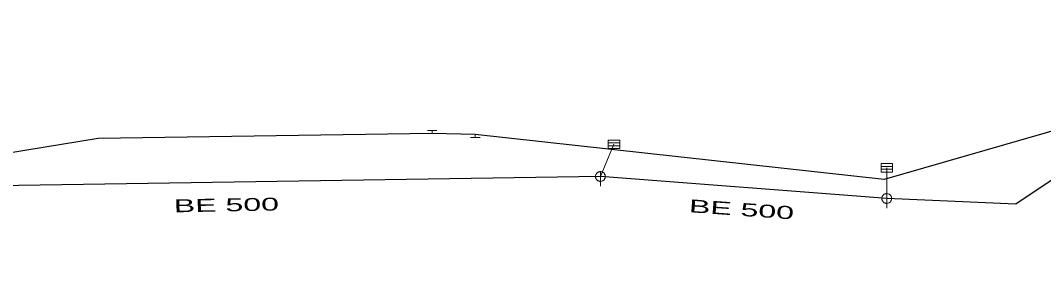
# Model space of a CAD drawing. Extents: x -687468 to -685917, y -974192 to -973456.
# Drawn here: x -686841 to -686788.4, y -973728.6 to -973716 of the extents above; entities that cross this region are included whole.
import ezdxf
from ezdxf.enums import TextEntityAlignment as Align

# ---------------------------------------------------------------- set-up
doc = ezdxf.new("R2010")
doc.units = 0
doc.header["$LTSCALE"] = 0.27
for name, color, linetype, lineweight in [('1', 7, 'Continuous', 13), ('11', 7, 'Continuous', 13), ('14', 7, 'Continuous', 25), ('17', 7, 'Continuous', 25), ('22', 7, 'Continuous', 13), ('34', 7, 'Continuous', 13)]:
    doc.layers.add(name, color=color, linetype=linetype, lineweight=lineweight)

msp = doc.modelspace()

# ---------------------------------------------------------------- linework, layer by layer
at = {"layer": '11'}
for p, q in [((-686810.51, -973722.38), (-686811.2, -973724.04)), ((-686796.46, -973723.59), (-686796.46, -973725.17))]:
    msp.add_line(p, q, dxfattribs=at)
at = {"layer": '14', "lineweight": 13}
for p, q in [((-686819.859, -973721.829), (-686819.859, -973721.669)), ((-686817.64, -973722.03), (-686817.64, -973721.882))]:
    msp.add_line(p, q, dxfattribs=at)
at = {"layer": '14'}
msp.add_line((-686796.46, -973725.17), (-686811.199, -973724.039), dxfattribs=at)
for points in [[(-686778.059, -973717.6), (-686789.822, -973725.456), (-686796.46, -973725.17)], [(-686811.199, -973724.039), (-686842.258, -973724.526), (-686849.73, -973724.67)]]:
    msp.add_lwpolyline(points, dxfattribs=at)
at = {"layer": '17'}
msp.add_lwpolyline([(-686778.16, -973716.008), (-686787.234, -973721.504), (-686796.6, -973724.188), (-686817.64, -973721.881), (-686819.859, -973721.829), (-686837.05, -973722.085), (-686859.074, -973725.682), (-686861.337, -973725.804), (-686883.709, -973728.57)], dxfattribs=at)
at = {"layer": '22'}
for p, q in [((-686810.805, -973722.309), (-686810.207, -973722.309)), ((-686810.805, -973722.455), (-686810.207, -973722.455)), ((-686796.755, -973723.519), (-686796.157, -973723.519)), ((-686796.755, -973723.664), (-686796.157, -973723.664)), ((-686811.198, -973723.787), (-686811.199, -973724.531)), ((-686796.459, -973724.918), (-686796.46, -973725.662))]:
    msp.add_line(p, q, dxfattribs=at)
for points in [[(-686810.805, -973722.163), (-686810.207, -973722.163), (-686810.207, -973722.6), (-686810.805, -973722.6)], [(-686796.755, -973723.373), (-686796.157, -973723.373), (-686796.157, -973723.809), (-686796.755, -973723.809)], [(-686810.947, -973724.039), (-686810.948, -973724.013), (-686810.952, -973723.987), (-686810.958, -973723.961), (-686810.968, -973723.937), (-686810.98, -973723.913), (-686810.994, -973723.891), (-686811.011, -973723.87), (-686811.029, -973723.852), (-686811.05, -973723.835), (-686811.072, -973723.821), (-686811.096, -973723.809), (-686811.12, -973723.799), (-686811.146, -973723.793), (-686811.172, -973723.789), (-686811.198, -973723.787), (-686811.224, -973723.788), (-686811.25, -973723.792), (-686811.276, -973723.798), (-686811.301, -973723.808), (-686811.324, -973723.82), (-686811.346, -973723.834), (-686811.367, -973723.851), (-686811.385, -973723.869), (-686811.402, -973723.89), (-686811.416, -973723.912), (-686811.428, -973723.936), (-686811.438, -973723.96), (-686811.445, -973723.986), (-686811.449, -973724.012), (-686811.451, -973724.038), (-686811.45, -973724.064), (-686811.446, -973724.09), (-686811.439, -973724.116), (-686811.429, -973724.141), (-686811.417, -973724.164), (-686811.403, -973724.186), (-686811.386, -973724.207), (-686811.368, -973724.225), (-686811.347, -973724.242), (-686811.325, -973724.256), (-686811.302, -973724.268), (-686811.277, -973724.278), (-686811.251, -973724.285), (-686811.225, -973724.289), (-686811.199, -973724.291), (-686811.173, -973724.29), (-686811.147, -973724.286), (-686811.121, -973724.279), (-686811.097, -973724.269), (-686811.073, -973724.257), (-686811.051, -973724.243), (-686811.03, -973724.226), (-686811.012, -973724.208), (-686810.995, -973724.187), (-686810.981, -973724.165), (-686810.969, -973724.142), (-686810.959, -973724.117), (-686810.953, -973724.091), (-686810.949, -973724.065)], [(-686796.208, -973725.17), (-686796.209, -973725.144), (-686796.213, -973725.118), (-686796.219, -973725.092), (-686796.229, -973725.068), (-686796.241, -973725.044), (-686796.255, -973725.022), (-686796.272, -973725.001), (-686796.29, -973724.983), (-686796.311, -973724.966), (-686796.333, -973724.952), (-686796.357, -973724.94), (-686796.381, -973724.93), (-686796.407, -973724.924), (-686796.433, -973724.92), (-686796.459, -973724.918), (-686796.485, -973724.919), (-686796.511, -973724.923), (-686796.537, -973724.929), (-686796.562, -973724.939), (-686796.585, -973724.951), (-686796.607, -973724.965), (-686796.628, -973724.982), (-686796.646, -973725), (-686796.663, -973725.021), (-686796.677, -973725.043), (-686796.689, -973725.067), (-686796.699, -973725.091), (-686796.706, -973725.117), (-686796.71, -973725.143), (-686796.712, -973725.169), (-686796.711, -973725.195), (-686796.707, -973725.221), (-686796.7, -973725.247), (-686796.69, -973725.272), (-686796.678, -973725.295), (-686796.664, -973725.317), (-686796.647, -973725.338), (-686796.629, -973725.356), (-686796.608, -973725.373), (-686796.586, -973725.387), (-686796.563, -973725.399), (-686796.538, -973725.409), (-686796.512, -973725.416), (-686796.486, -973725.42), (-686796.46, -973725.422), (-686796.434, -973725.421), (-686796.408, -973725.417), (-686796.382, -973725.41), (-686796.358, -973725.4), (-686796.334, -973725.388), (-686796.312, -973725.374), (-686796.291, -973725.357), (-686796.273, -973725.339), (-686796.256, -973725.318), (-686796.242, -973725.296), (-686796.23, -973725.273), (-686796.22, -973725.248), (-686796.214, -973725.222), (-686796.21, -973725.196)]]:
    msp.add_lwpolyline(points, close=True, dxfattribs=at)
at = {"layer": '34'}
for p, q in [((-686820.106, -973721.67), (-686819.611, -973721.667)), ((-686817.392, -973722.03), (-686817.888, -973722.029))]:
    msp.add_line(p, q, dxfattribs=at)

# ---------------------------------------------------------------- texts
at = {"layer": '1', "width": 1.85}
for rotation, p in [(1, (-686830.445, -973725.836)), (356, (-686803.957, -973726.063))]:
    msp.add_text('BE 500', height=0.6667, rotation=rotation, dxfattribs=at).set_placement(p, align=Align.CENTER)

doc.saveas('drawing.dxf')
